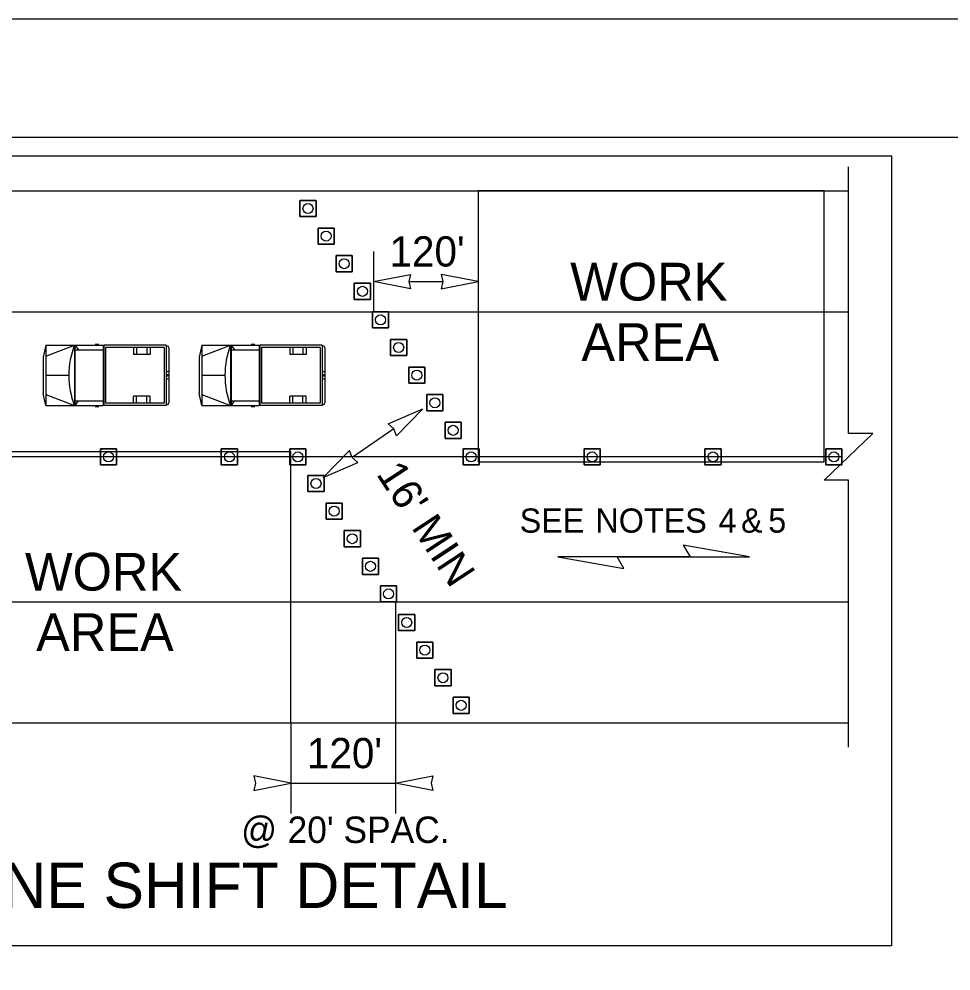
# Model space of a CAD drawing. Extents: x 99998.9 to 100095.7, y 99995 to 100010.7.
# Drawn here: x 100007.305 to 100009.772, y 100008.167 to 100010.687 of the extents above; entities that cross this region are included whole.
import ezdxf

# ---------------------------------------------------------------- set-up
doc = ezdxf.new("R2010")
doc.units = 0
for name, color, linetype in [('RD_ED_ShoulderPavedEdge', 7, 'Continuous'), ('RD_MK_LineEdgeWhite', 7, 'Continuous'), ('RD_MK_LineSkipCenter', 7, 'Continuous'), ('SH_DE_DetailHeading2Text', 7, 'Continuous'), ('SH_GI_PlotLimits', 7, 'Continuous'), ('SH_GI_SheetBorder', 7, 'Continuous'), ('SH_TI_Tables', 7, 'Continuous'), ('TR_WZ_MotoristVehicle', 7, 'Continuous'), ('TR_WZ_TrafficCone', 7, 'Continuous'), ('TR_WZ_WorkAreaLabel', 7, 'Continuous'), ('TR_WZ_WorkZoneDetails', 7, 'Continuous'), ('TR_WZ_WorkZoneTextCurrent', 7, 'Continuous')]:
    doc.layers.add(name, color=color, linetype=linetype)

msp = doc.modelspace()

# ---------------------------------------------------------------- linework, layer by layer
at = {"layer": 'RD_ED_ShoulderPavedEdge'}
for p, q in [((100005.5832, 100010.2323), (100009.5005, 100010.2323)), ((100005.5832, 100008.8243), (100009.5005, 100008.8243))]:
    msp.add_line(p, q, dxfattribs=at)
at = {"layer": 'RD_MK_LineEdgeWhite'}
for p, q in [((100005.5832, 100009.9123), (100009.5005, 100009.9123)), ((100005.5832, 100009.1443), (100009.5005, 100009.1443))]:
    msp.add_line(p, q, dxfattribs=at)
at = {"layer": 'RD_MK_LineSkipCenter'}
msp.add_lwpolyline([(100009.484, 100009.5283), (100005.5667, 100009.5283)], dxfattribs=at)
at = {"layer": 'SH_GI_PlotLimits'}
msp.add_lwpolyline([(99999.0625, 99999.6875), (100016.0625, 99999.6875), (100016.0625, 100010.6875), (99999.0625, 100010.6875)], close=True, dxfattribs=at)
at = {"layer": 'SH_GI_SheetBorder'}
msp.add_line((100000, 100010.375), (100015.75, 100010.375), dxfattribs=at)
at = {"layer": 'SH_TI_Tables'}
msp.add_lwpolyline([(100005.4692, 100010.325), (100009.6146, 100010.325), (100009.6146, 100008.2343), (100005.4692, 100008.2343)], close=True, dxfattribs=at)
at = {"layer": 'TR_WZ_MotoristVehicle'}
for p, q in [((100007.3763, 100009.8243), (100007.3689, 100009.792)), ((100007.3763, 100009.8243), (100007.3763, 100009.6643)), ((100007.3763, 100009.8243), (100007.5274, 100009.8243)), ((100007.3763, 100009.795), (100007.4518, 100009.8243)), ((100007.4518, 100009.8243), (100007.4518, 100009.6643)), ((100007.4532, 100009.8243), (100007.4532, 100009.6643)), ((100007.4532, 100009.8243), (100007.4628, 100009.8119)), ((100007.4532, 100009.8119), (100007.5274, 100009.8119)), ((100007.5068, 100009.8266), (100007.5159, 100009.8266)), ((100007.5274, 100009.8243), (100007.5274, 100009.6643)), ((100007.6942, 100009.8243), (100007.5296, 100009.8243)), ((100007.5296, 100009.8243), (100007.5296, 100009.6643)), ((100007.6895, 100009.8179), (100007.5343, 100009.8179)), ((100007.5343, 100009.8179), (100007.5343, 100009.6707)), ((100007.6085, 100009.8179), (100007.6085, 100009.7995)), ((100007.6164, 100009.8179), (100007.6164, 100009.7995)), ((100007.6436, 100009.8179), (100007.6436, 100009.7995)), ((100007.6524, 100009.8179), (100007.6524, 100009.7995)), ((100007.6895, 100009.8179), (100007.6895, 100009.6707)), ((100007.6942, 100009.8243), (100007.6942, 100009.6643)), ((100007.6983, 100009.8217), (100007.6947, 100009.8217)), ((100007.6947, 100009.8217), (100007.6947, 100009.667)), ((100007.7019, 100009.8168), (100007.7019, 100009.6718)), ((100007.7893, 100009.8243), (100007.7819, 100009.792)), ((100007.7893, 100009.8243), (100007.7893, 100009.6643)), ((100007.7893, 100009.8243), (100007.9404, 100009.8243)), ((100007.7893, 100009.795), (100007.8649, 100009.8243)), ((100007.8649, 100009.8243), (100007.8649, 100009.6643)), ((100007.8662, 100009.8243), (100007.8662, 100009.6643)), ((100007.8662, 100009.8243), (100007.8758, 100009.8119)), ((100007.8662, 100009.8119), (100007.9404, 100009.8119)), ((100007.9198, 100009.8266), (100007.9289, 100009.8266)), ((100007.9404, 100009.8243), (100007.9404, 100009.6643)), ((100008.1072, 100009.8243), (100007.9426, 100009.8243)), ((100007.9426, 100009.8243), (100007.9426, 100009.6643)), ((100008.1025, 100009.8179), (100007.9473, 100009.8179)), ((100007.9473, 100009.8179), (100007.9473, 100009.6707)), ((100008.0215, 100009.8179), (100008.0215, 100009.7995)), ((100008.0294, 100009.8179), (100008.0294, 100009.7995)), ((100008.0566, 100009.8179), (100008.0566, 100009.7995)), ((100008.0654, 100009.8179), (100008.0654, 100009.7995)), ((100008.1025, 100009.8179), (100008.1025, 100009.6707)), ((100008.1072, 100009.8243), (100008.1072, 100009.6643)), ((100008.1113, 100009.8217), (100008.1077, 100009.8217)), ((100008.1077, 100009.8217), (100008.1077, 100009.667)), ((100008.1149, 100009.8168), (100008.1149, 100009.6718)), ((100007.3689, 100009.792), (100007.3689, 100009.6966)), ((100007.6524, 100009.7995), (100007.6085, 100009.7995)), ((100007.7819, 100009.792), (100007.7819, 100009.6966)), ((100008.0654, 100009.7995), (100008.0215, 100009.7995)), ((100007.3763, 100009.7443), (100007.437, 100009.7443)), ((100007.7019, 100009.7556), (100007.6947, 100009.7526)), ((100007.7, 100009.7443), (100007.6967, 100009.7443)), ((100007.6983, 100009.7466), (100007.6983, 100009.7421)), ((100007.7893, 100009.7443), (100007.85, 100009.7443)), ((100008.1149, 100009.7556), (100008.1077, 100009.7526)), ((100008.113, 100009.7443), (100008.1097, 100009.7443)), ((100008.1113, 100009.7466), (100008.1113, 100009.7421)), ((100007.7019, 100009.7331), (100007.6947, 100009.7361)), ((100008.1149, 100009.7331), (100008.1077, 100009.7361)), ((100007.3763, 100009.6643), (100007.3689, 100009.6966)), ((100007.3763, 100009.6936), (100007.4518, 100009.6643)), ((100007.6085, 100009.6707), (100007.6085, 100009.6891)), ((100007.6524, 100009.6891), (100007.6085, 100009.6891)), ((100007.6164, 100009.6707), (100007.6164, 100009.6891)), ((100007.6436, 100009.6707), (100007.6436, 100009.6891)), ((100007.6524, 100009.6707), (100007.6524, 100009.6891)), ((100007.7893, 100009.6643), (100007.7819, 100009.6966)), ((100007.7893, 100009.6936), (100007.8649, 100009.6643)), ((100008.0215, 100009.6707), (100008.0215, 100009.6891)), ((100008.0654, 100009.6891), (100008.0215, 100009.6891)), ((100008.0294, 100009.6707), (100008.0294, 100009.6891)), ((100008.0566, 100009.6707), (100008.0566, 100009.6891)), ((100008.0654, 100009.6707), (100008.0654, 100009.6891)), ((100007.3763, 100009.6643), (100007.5274, 100009.6643)), ((100007.4532, 100009.6767), (100007.5274, 100009.6767)), ((100007.4612, 100009.6767), (100007.4532, 100009.6643)), ((100007.5068, 100009.6621), (100007.5159, 100009.6621)), ((100007.6942, 100009.6643), (100007.5296, 100009.6643)), ((100007.6895, 100009.6707), (100007.5343, 100009.6707)), ((100007.6983, 100009.667), (100007.6947, 100009.667)), ((100007.7893, 100009.6643), (100007.9404, 100009.6643)), ((100007.8662, 100009.6767), (100007.9404, 100009.6767)), ((100007.8742, 100009.6767), (100007.8662, 100009.6643)), ((100007.9198, 100009.6621), (100007.9289, 100009.6621)), ((100008.1072, 100009.6643), (100007.9426, 100009.6643)), ((100008.1025, 100009.6707), (100007.9473, 100009.6707)), ((100008.1113, 100009.667), (100008.1077, 100009.667))]:
    msp.add_line(p, q, dxfattribs=at)
for centre, major_axis, start_param, end_param in [((100007.5598, 100009.7443), (0, -0.1679), 4.215667, 5.208926), ((100007.6983, 100009.8168), (0, 0.00488), 4.712389, 6.283185), ((100007.9729, 100009.7443), (0, -0.1679), 4.215667, 5.208926), ((100008.1113, 100009.8168), (0, 0.00488), 4.712389, 6.283185), ((100007.6983, 100009.6718), (0, -0.00488), 0, 1.570796), ((100008.1113, 100009.6718), (0, -0.00488), 0, 1.570796)]:
    msp.add_ellipse(centre, major_axis=major_axis, ratio=0.73155, start_param=start_param, end_param=end_param, dxfattribs=at)
for centre in [(100007.6983, 100009.7443), (100008.1113, 100009.7443)]:
    msp.add_ellipse(centre, major_axis=(0, 0.00225), ratio=0.73155, dxfattribs=at)
at = {"layer": 'TR_WZ_TrafficCone'}
for points in [[(100008.0485, 100010.2073), (100008.0912, 100010.2073), (100008.0912, 100010.1646), (100008.0485, 100010.1646), (100008.0485, 100010.2073)], [(100008.0485, 100010.1646), (100008.0912, 100010.1646), (100008.0912, 100010.2073), (100008.0485, 100010.2073), (100008.0485, 100010.1646)], [(100008.0965, 100010.1342), (100008.1392, 100010.1342), (100008.1392, 100010.0915), (100008.0965, 100010.0915), (100008.0965, 100010.1342)], [(100008.0965, 100010.0915), (100008.1392, 100010.0915), (100008.1392, 100010.1342), (100008.0965, 100010.1342), (100008.0965, 100010.0915)], [(100008.1445, 100010.0611), (100008.1872, 100010.0611), (100008.1872, 100010.0185), (100008.1445, 100010.0185), (100008.1445, 100010.0611)], [(100008.1445, 100010.0185), (100008.1872, 100010.0185), (100008.1872, 100010.0611), (100008.1445, 100010.0611), (100008.1445, 100010.0185)], [(100008.1925, 100009.9881), (100008.2352, 100009.9881), (100008.2352, 100009.9454), (100008.1925, 100009.9454), (100008.1925, 100009.9881)], [(100008.1925, 100009.9454), (100008.2352, 100009.9454), (100008.2352, 100009.9881), (100008.1925, 100009.9881), (100008.1925, 100009.9454)], [(100008.2406, 100009.9123), (100008.2832, 100009.9123), (100008.2832, 100009.8697), (100008.2406, 100009.8697), (100008.2406, 100009.9123)], [(100008.2406, 100009.8697), (100008.2832, 100009.8697), (100008.2832, 100009.9123), (100008.2406, 100009.9123), (100008.2406, 100009.8697)], [(100008.2886, 100009.8393), (100008.3312, 100009.8393), (100008.3312, 100009.7966), (100008.2886, 100009.7966), (100008.2886, 100009.8393)], [(100008.2886, 100009.7966), (100008.3312, 100009.7966), (100008.3312, 100009.8393), (100008.2886, 100009.8393), (100008.2886, 100009.7966)], [(100008.3366, 100009.7662), (100008.3792, 100009.7662), (100008.3792, 100009.7235), (100008.3366, 100009.7235), (100008.3366, 100009.7662)], [(100008.3366, 100009.7235), (100008.3792, 100009.7235), (100008.3792, 100009.7662), (100008.3366, 100009.7662), (100008.3366, 100009.7235)], [(100008.3846, 100009.6931), (100008.4272, 100009.6931), (100008.4272, 100009.6505), (100008.3846, 100009.6505), (100008.3846, 100009.6931)], [(100008.3846, 100009.6505), (100008.4272, 100009.6505), (100008.4272, 100009.6931), (100008.3846, 100009.6931), (100008.3846, 100009.6505)], [(100008.4326, 100009.6201), (100008.4752, 100009.6201), (100008.4752, 100009.5774), (100008.4326, 100009.5774), (100008.4326, 100009.6201)], [(100008.4326, 100009.5774), (100008.4752, 100009.5774), (100008.4752, 100009.6201), (100008.4326, 100009.6201), (100008.4326, 100009.5774)], [(100007.5205, 100009.5497), (100007.5632, 100009.5497), (100007.5632, 100009.507), (100007.5205, 100009.507), (100007.5205, 100009.5497)], [(100007.5205, 100009.507), (100007.5632, 100009.507), (100007.5632, 100009.5497), (100007.5205, 100009.5497), (100007.5205, 100009.507)], [(100007.8405, 100009.5497), (100007.8832, 100009.5497), (100007.8832, 100009.507), (100007.8405, 100009.507), (100007.8405, 100009.5497)], [(100007.8405, 100009.507), (100007.8832, 100009.507), (100007.8832, 100009.5497), (100007.8405, 100009.5497), (100007.8405, 100009.507)], [(100008.0219, 100009.5497), (100008.0646, 100009.5497), (100008.0646, 100009.507), (100008.0219, 100009.507), (100008.0219, 100009.5497)], [(100008.0219, 100009.507), (100008.0646, 100009.507), (100008.0646, 100009.5497), (100008.0219, 100009.5497), (100008.0219, 100009.507)], [(100008.5232, 100009.5497), (100008.4805, 100009.5497), (100008.4805, 100009.507), (100008.5232, 100009.507), (100008.5232, 100009.5497)], [(100008.5232, 100009.507), (100008.4805, 100009.507), (100008.4805, 100009.5497), (100008.5232, 100009.5497), (100008.5232, 100009.507)], [(100008.8005, 100009.5497), (100008.8432, 100009.5497), (100008.8432, 100009.507), (100008.8005, 100009.507), (100008.8005, 100009.5497)], [(100008.8005, 100009.507), (100008.8432, 100009.507), (100008.8432, 100009.5497), (100008.8005, 100009.5497), (100008.8005, 100009.507)], [(100009.1205, 100009.5497), (100009.1632, 100009.5497), (100009.1632, 100009.507), (100009.1205, 100009.507), (100009.1205, 100009.5497)], [(100009.1205, 100009.507), (100009.1632, 100009.507), (100009.1632, 100009.5497), (100009.1205, 100009.5497), (100009.1205, 100009.507)], [(100009.4405, 100009.5497), (100009.4832, 100009.5497), (100009.4832, 100009.507), (100009.4405, 100009.507), (100009.4405, 100009.5497)], [(100009.4405, 100009.507), (100009.4832, 100009.507), (100009.4832, 100009.5497), (100009.4405, 100009.5497), (100009.4405, 100009.507)], [(100008.1125, 100009.4366), (100008.0699, 100009.4366), (100008.0699, 100009.4793), (100008.1125, 100009.4793), (100008.1125, 100009.4366)], [(100008.1125, 100009.4793), (100008.0699, 100009.4793), (100008.0699, 100009.4366), (100008.1125, 100009.4366), (100008.1125, 100009.4793)], [(100008.1605, 100009.3635), (100008.1179, 100009.3635), (100008.1179, 100009.4062), (100008.1605, 100009.4062), (100008.1605, 100009.3635)], [(100008.1605, 100009.4062), (100008.1179, 100009.4062), (100008.1179, 100009.3635), (100008.1605, 100009.3635), (100008.1605, 100009.4062)], [(100008.2085, 100009.2905), (100008.1659, 100009.2905), (100008.1659, 100009.3331), (100008.2085, 100009.3331), (100008.2085, 100009.2905)], [(100008.2085, 100009.3331), (100008.1659, 100009.3331), (100008.1659, 100009.2905), (100008.2085, 100009.2905), (100008.2085, 100009.3331)], [(100008.2565, 100009.2174), (100008.2139, 100009.2174), (100008.2139, 100009.2601), (100008.2565, 100009.2601), (100008.2565, 100009.2174)], [(100008.2565, 100009.2601), (100008.2139, 100009.2601), (100008.2139, 100009.2174), (100008.2565, 100009.2174), (100008.2565, 100009.2601)], [(100008.3045, 100009.1443), (100008.2619, 100009.1443), (100008.2619, 100009.187), (100008.3045, 100009.187), (100008.3045, 100009.1443)], [(100008.3045, 100009.187), (100008.2619, 100009.187), (100008.2619, 100009.1443), (100008.3045, 100009.1443), (100008.3045, 100009.187)], [(100008.3099, 100009.1113), (100008.3526, 100009.1113), (100008.3526, 100009.0686), (100008.3099, 100009.0686), (100008.3099, 100009.1113)], [(100008.3099, 100009.0686), (100008.3526, 100009.0686), (100008.3526, 100009.1113), (100008.3099, 100009.1113), (100008.3099, 100009.0686)], [(100008.3579, 100009.0382), (100008.4006, 100009.0382), (100008.4006, 100008.9955), (100008.3579, 100008.9955), (100008.3579, 100009.0382)], [(100008.3579, 100008.9955), (100008.4006, 100008.9955), (100008.4006, 100009.0382), (100008.3579, 100009.0382), (100008.3579, 100008.9955)], [(100008.4059, 100008.9651), (100008.4486, 100008.9651), (100008.4486, 100008.9225), (100008.4059, 100008.9225), (100008.4059, 100008.9651)], [(100008.4059, 100008.9225), (100008.4486, 100008.9225), (100008.4486, 100008.9651), (100008.4059, 100008.9651), (100008.4059, 100008.9225)], [(100008.4539, 100008.8921), (100008.4966, 100008.8921), (100008.4966, 100008.8494), (100008.4539, 100008.8494), (100008.4539, 100008.8921)], [(100008.4539, 100008.8494), (100008.4966, 100008.8494), (100008.4966, 100008.8921), (100008.4539, 100008.8921), (100008.4539, 100008.8494)]]:
    msp.add_lwpolyline(points, dxfattribs=at)
for centre in [(100008.0699, 100010.1859), (100008.1179, 100010.1129), (100008.1659, 100010.0398), (100008.2139, 100009.9667), (100008.2619, 100009.891), (100008.3099, 100009.8179), (100008.3579, 100009.7449), (100008.4059, 100009.6718), (100008.4539, 100009.5987), (100007.5419, 100009.5283), (100007.8619, 100009.5283), (100008.0433, 100009.5283), (100008.5018, 100009.5283), (100008.8219, 100009.5283), (100009.1419, 100009.5283), (100009.4619, 100009.5283), (100008.0912, 100009.4579), (100008.1392, 100009.3849), (100008.1872, 100009.3118), (100008.2352, 100009.2387), (100008.2832, 100009.1657), (100008.3312, 100009.0899), (100008.3792, 100009.0169), (100008.4272, 100008.9438), (100008.4752, 100008.8707)]:
    msp.add_circle(centre, 0.0133, dxfattribs=at)
at = {"layer": 'TR_WZ_WorkZoneDetails'}
for p, q in [((100008.2432, 100010.0723), (100008.2432, 100009.9123)), ((100008.5205, 100010.0723), (100008.5205, 100009.9123)), ((100008.3369, 100009.9923), (100008.4268, 100009.9923)), ((100008.297, 100009.6027), (100008.1871, 100009.5271)), ((100008.8883, 100009.2638), (100009.0812, 100009.2638)), ((100009.0812, 100009.2638), (100008.8883, 100009.2638)), ((100008.3019, 100009.1443), (100008.3019, 100008.5843)), ((100008.0246, 100008.8243), (100008.0246, 100008.5843)), ((100008.0246, 100008.6643), (100008.3019, 100008.6643))]:
    msp.add_line(p, q, dxfattribs=at)
msp.add_lwpolyline([(100009.5005, 100008.7603), (100009.5005, 100009.4664), (100009.4365, 100009.4664), (100009.5646, 100009.5903), (100009.5005, 100009.5903), (100009.5005, 100010.2963)], dxfattribs=at)
for points in [[(100008.5205, 100010.2323), (100008.5205, 100009.515), (100009.4365, 100009.515), (100009.4365, 100010.2323)], [(100008.2432, 100009.9923), (100008.3415, 100010.0116), (100008.3369, 100009.9923), (100008.3415, 100009.9731)], [(100008.5205, 100009.9923), (100008.4223, 100010.0116), (100008.4268, 100009.9923), (100008.4223, 100009.9731)], [(100008.3742, 100009.6558), (100008.3042, 100009.5842), (100008.297, 100009.6027), (100008.2823, 100009.616)], [(100007.0462, 100009.5417), (100007.0462, 100008.8243), (100008.0246, 100008.8243), (100008.0246, 100009.5417)], [(100008.1099, 100009.4739), (100008.2018, 100009.5138), (100008.1871, 100009.5271), (100008.1799, 100009.5455)], [(100009.2384, 100009.2638), (100009.0633, 100009.2946), (100009.0812, 100009.2638)], [(100008.731, 100009.2638), (100008.9061, 100009.2329), (100008.8883, 100009.2638)], [(100008.0246, 100008.6643), (100007.9263, 100008.6836), (100007.9308, 100008.6643), (100007.9263, 100008.6451)], [(100008.3019, 100008.6643), (100008.4002, 100008.6836), (100008.3956, 100008.6643), (100008.4002, 100008.6451)]]:
    msp.add_lwpolyline(points, close=True, dxfattribs=at)

# ---------------------------------------------------------------- texts
at = {"layer": 'SH_DE_DetailHeading2Text'}
msp.add_text('OPTIONAL LANE SHIFT DETAIL', height=0.12, rotation=360, dxfattribs=at).set_placement((100006.209, 100008.3343))
at = {"layer": 'TR_WZ_WorkAreaLabel'}
for s, p in [('WORK', (100008.764, 100009.9423)), ('AREA', (100008.7936, 100009.7823)), ('WORK', (100007.3208, 100009.1743)), ('AREA', (100007.3505, 100009.0143))]:
    msp.add_text(s, height=0.1, dxfattribs=at).set_placement(p)
at = {"layer": 'TR_WZ_WorkZoneTextCurrent'}
for s, height, rotation, p in [("120'", 0.08, 360, (100008.2857, 100010.0323)), ("16' MIN", 0.08, 303.3023, (100008.2491, 100009.4829)), ("120'", 0.08, 360, (100008.0671, 100008.7043)), ('@', 0.07, 360, (100007.893, 100008.5063)), ("20' SPAC.", 0.07, 360, (100008.0159, 100008.5063))]:
    msp.add_text(s, height=height, rotation=rotation, dxfattribs=at).set_placement(p)
for s, p in [('SEE', (100008.6302, 100009.3278)), ('NOTES', (100008.8307, 100009.3278)), ('4', (100009.1567, 100009.3278)), ('&', (100009.2162, 100009.3278)), ('5', (100009.2881, 100009.3278))]:
    msp.add_text(s, height=0.064, dxfattribs=at).set_placement(p)

doc.saveas('drawing.dxf')
